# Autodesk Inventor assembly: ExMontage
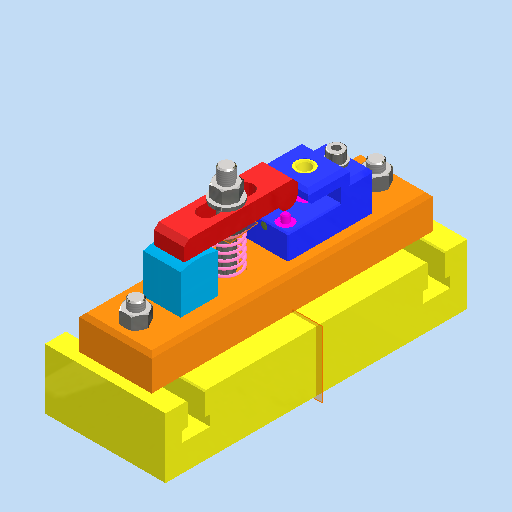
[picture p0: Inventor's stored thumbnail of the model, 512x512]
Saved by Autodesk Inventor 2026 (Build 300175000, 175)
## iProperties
Created: 2025-12
Part Number: ExMontage
Document SubType Name: Assembly
Designer: thierry.jost
Author: thierry.jost
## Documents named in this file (20)
- \\Client\H$\CD\CD1\COURS\9-FILTAGE\ExMontage\ExMontage.iam
- \\Client\H$\CD\CD1\COURS\9-FILTAGE\ExMontage\19-Table.ipt
- \\Client\H$\CD\CD1\COURS\9-FILTAGE\ExMontage\01-Pied.ipt
- \\Client\H$\CD\CD1\COURS\9-FILTAGE\ExMontage\02-PortePiece.ipt
- \\Client\H$\CD\CD1\COURS\9-FILTAGE\ExMontage\14-Bague.ipt
- \\Client\H$\CD\CD1\COURS\9-FILTAGE\ExMontage\17-Picot.ipt
- \\Client\H$\CD\CD1\COURS\9-FILTAGE\ExMontage\18-PetitPicot.ipt
- \\Client\H$\CD\CD1\COURS\9-FILTAGE\ExMontage\05-Plot.ipt
- \\Client\H$\CD\CD1\COURS\9-FILTAGE\ExMontage\03-Bride.ipt
- \\Client\H$\CD\CD1\COURS\9-FILTAGE\ExMontage\11-Rondelle.ipt
- C:\Users\thierry.jost\Documents\Inventor\Content Center Files\R2026\fr-FR\NF E 25-118 - C\NF E 25-118 - M12 x 65.ipt
- C:\Users\thierry.jost\Documents\Inventor\Content Center Files\R2026\fr-FR\ISO 4032(3)\ISO 4032 - M12NF EN.ipt
- C:\Users\thierry.jost\Documents\Inventor\Content Center Files\R2026\fr-FR\NF E 25-510\NF E 25-510 - CL 10 x 20.ipt
- C:\Users\thierry.jost\Documents\Inventor\Content Center Files\R2026\fr-FR\NF E 25-125\NF E 25-125 - M10 x 30.ipt
- C:\Users\thierry.jost\Documents\Inventor\Content Center Files\R2026\fr-FR\NF E 25-125\NF E 25-125 - M8 x 45.ipt
- C:\Users\thierry.jost\Documents\Inventor\Content Center Files\R2026\fr-FR\NF E 25-510\NF E 25-510 - CL 8 x 16.ipt
- \\Client\H$\CD\CD1\COURS\9-FILTAGE\ExMontage\04-Ressort.ipt
- C:\Users\thierry.jost\Documents\Inventor\Content Center Files\R2026\fr-FR\NF E 25-135\NF E25-135 - M12 x 75 (1 x d) x 30.ipt
- C:\Users\thierry.jost\Documents\Inventor\Content Center Files\R2026\fr-FR\NF E 25-510\NF E 25-510 - CL 12 x 24.ipt
- \\Client\H$\CD\CD1\COURS\9-FILTAGE\ExMontage\09-ISO 4032 - M12NF EN.ipt
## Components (25 placed, 18 different names)
1. 01-Pied:1
2. 02-PortePiece:1
3. 14-Bague:1 — Logement:2
4. 17-Picot:1 — Logement:3
5. 17-Picot:2 — Logement:5
6. 17-Picot:3 — Logement:4
7. 18-PetitPicot:1 — Logement:6
8. 05-Plot:1 — Logement:7, Angle:2, Tangente:1, Affleurement:1, Affleurement:2
9. 03-Bride:1 — Tangente:1, Affleurement:1, Placage:1, Placage:2, Placage:3, Affleurement:2
10. 11-Rondelle:1 — Placage:1, Placage:2, Placage:3
11. 19-Table:2 — Placage:4, Placage:5, Placage:6, Affleurement:4, Placage:7, Affleurement:5, Placage:8
12. NF E 25-118 - C M12 x 65:1 — Placage:7, Affleurement:5, Placage:8, Logement:9
13. NF E 25-118 - C M12 x 65:2 — Placage:5, Placage:6, Affleurement:4, Logement:8
14. NF EN 24032 M12:1
15. NF EN 24032 M12:2
16. NF E 25-510 CL 10 x 20:1 — Logement:12, Logement:15
17. NF E 25-510 CL 10 x 20:2 — Logement:13, Logement:14
18. NF E 25-125 M10 x 30:1 — Logement:14
19. NF E 25-125 M10 x 30:2 — Logement:15
20. NF E 25-125 M8 x 45:1 — Placage:10
21. NF E 25-510 CL 8 x 16:1 — Placage:10, Logement:16
22. 04-Ressort:1 — Affleurement:6, Placage:11
23. NF E 25-135 M12 x 75 (1 x d):1 — Logement:17, Logement:18
24. NF E 25-510 CL 12 x 24:1 — Logement:18, Logement:19
25. NF EN 24032 M12:3 — Logement:19
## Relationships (33: Insert 16, Mate 10, Flush 5, Angle 1, Tangent 1)
- Logement:2 [Insert]: 14-Bague:1
- Logement:3 [Insert]: 17-Picot:1
- Logement:4 [Insert]: 17-Picot:3
- Logement:5 [Insert]: 17-Picot:2
- Logement:6 [Insert]: 18-PetitPicot:1
- Logement:7 [Insert]: 05-Plot:1
- Angle:2: 05-Plot:1
- Tangente:1: 05-Plot:1 ↔ 03-Bride:1
- Affleurement:1 [Flush]: 05-Plot:1 ↔ 03-Bride:1
- Placage:1 [Mate]: 03-Bride:1 ↔ 11-Rondelle:1
- Placage:2 [Mate]: 03-Bride:1 ↔ 11-Rondelle:1
- Placage:3 [Mate]: 03-Bride:1 ↔ 11-Rondelle:1
- Affleurement:2 [Flush]: 05-Plot:1 ↔ 03-Bride:1
- Placage:4 [Mate]: 19-Table:2
- Placage:5 [Mate]: 19-Table:2 ↔ NF E 25-118 - C M12 x 65:2
- Placage:6 [Mate]: 19-Table:2 ↔ NF E 25-118 - C M12 x 65:2
- Affleurement:4 [Flush]: 19-Table:2 ↔ NF E 25-118 - C M12 x 65:2
- Logement:8 [Insert]: NF E 25-118 - C M12 x 65:2
- Placage:7 [Mate]: 19-Table:2 ↔ NF E 25-118 - C M12 x 65:1
- Affleurement:5 [Flush]: 19-Table:2 ↔ NF E 25-118 - C M12 x 65:1
- Placage:8 [Mate]: 19-Table:2 ↔ NF E 25-118 - C M12 x 65:1
- Logement:9 [Insert]: NF E 25-118 - C M12 x 65:1
- Logement:12 [Insert]: NF E 25-510 CL 10 x 20:1
- Logement:13 [Insert]: NF E 25-510 CL 10 x 20:2
- Logement:14 [Insert]: NF E 25-510 CL 10 x 20:2 ↔ NF E 25-125 M10 x 30:1
- Logement:15 [Insert]: NF E 25-510 CL 10 x 20:1 ↔ NF E 25-125 M10 x 30:2
- Placage:10 [Mate]: NF E 25-125 M8 x 45:1 ↔ NF E 25-510 CL 8 x 16:1
- Logement:16 [Insert]: NF E 25-510 CL 8 x 16:1
- Affleurement:6 [Flush]: 04-Ressort:1
- Placage:11 [Mate]: 04-Ressort:1
- Logement:17 [Insert]: NF E 25-135 M12 x 75 (1 x d):1
- Logement:18 [Insert]: NF E 25-135 M12 x 75 (1 x d):1 ↔ NF E 25-510 CL 12 x 24:1
- Logement:19 [Insert]: NF E 25-510 CL 12 x 24:1 ↔ NF EN 24032 M12:3
